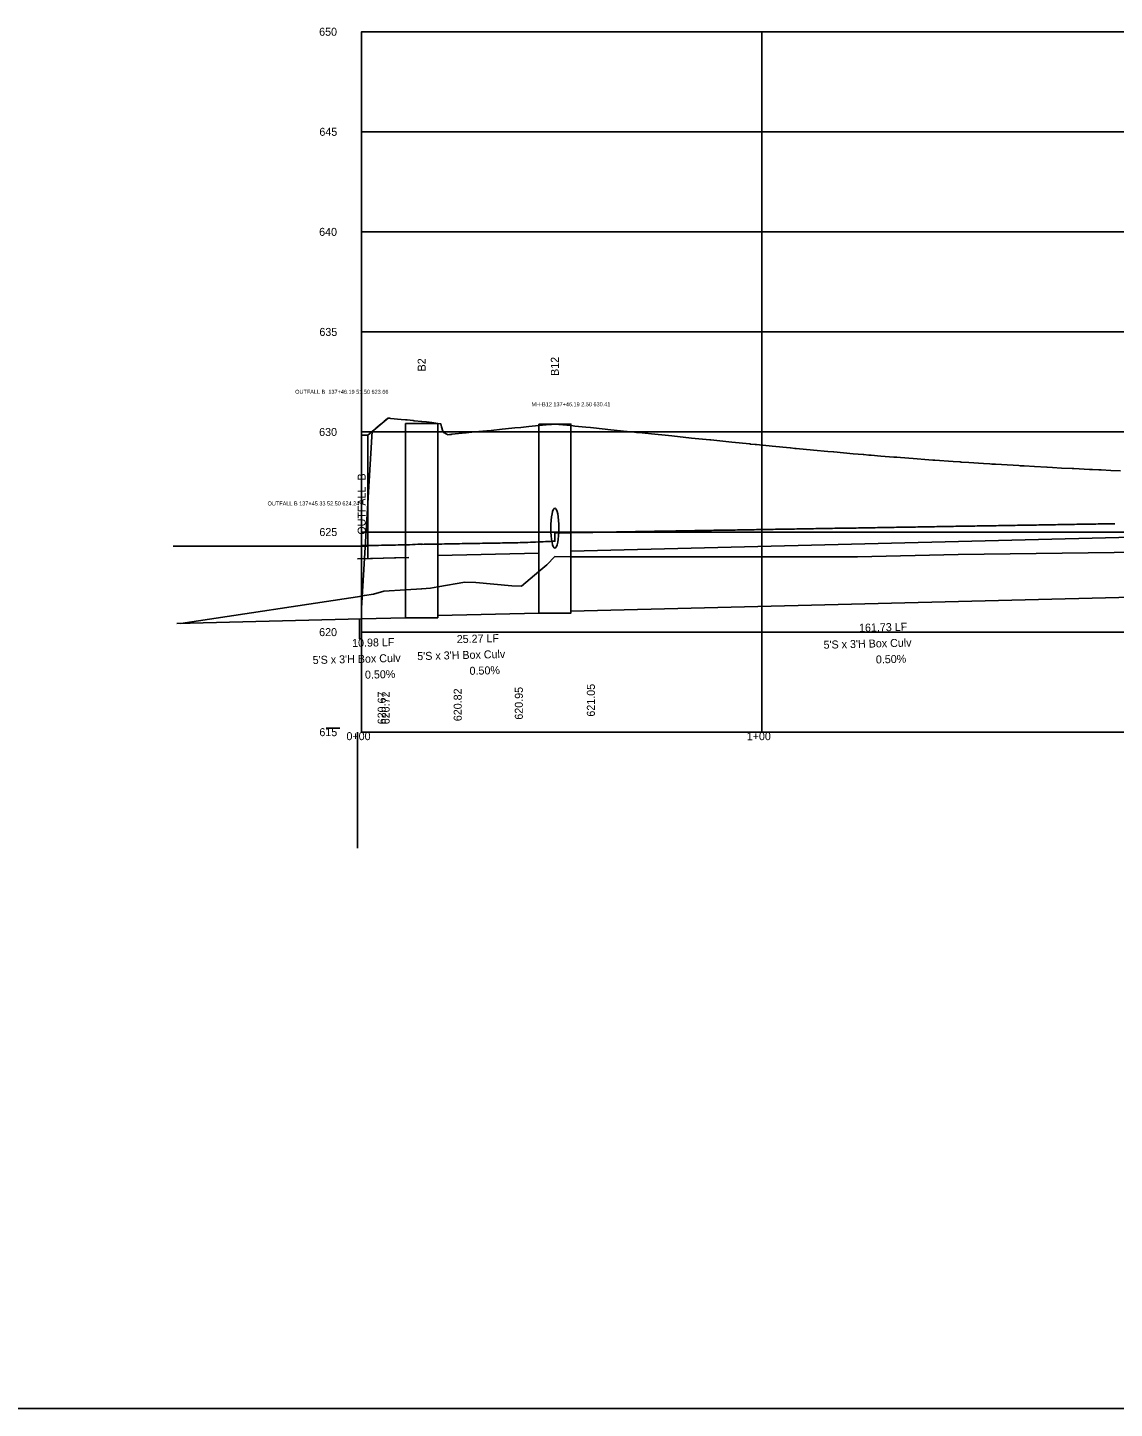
# Model space of a CAD drawing. Extents: x 2253035 to 2279930, y 13774972 to 13793443.
# Drawn here: x 2259878 to 2260149.5, y 13791972.5 to 13792317.5 of the extents above; entities that cross this region are included whole.
import ezdxf

# ---------------------------------------------------------------- set-up
doc = ezdxf.new("R2010")
doc.units = 0
for name, color, linetype in [('Default', 7, 'Continuous'), ('E_Utility_ATT_HH', 7, 'Continuous'), ('E_Utility_ATT_PR_PVC', 7, 'Continuous'), ('E_Utility_Electric_Service Pole Electric_SPLE_Description', 7, 'Continuous'), ('E_Utility_Telephone_Manhole Telephone_MHT_Description', 7, 'Continuous'), ('E_Utility_Telephone_Telephone Pedestal_TPED_Description', 7, 'Continuous'), ('E_Utility_Water_Fire Hydrant_FH_Description', 7, 'Continuous'), ('E_Utillity_Water_Water Line_12in', 7, 'Continuous'), ('E_Utillity_Water_Water Line_1in', 7, 'Continuous'), ('E_Utillity_Water_Water Line_4in', 7, 'Continuous'), ('E_Utillity_Water_Water Line_8in', 7, 'Continuous')]:
    doc.layers.add(name, color=color, linetype=linetype)

msp = doc.modelspace()

# ---------------------------------------------------------------- linework, layer by layer
at = {"layer": 'Default'}
for p, q in [((2260061.48, 13792141.44), (2260061.48, 13792316.44)), ((2259961.48, 13792291.44), (2261350.66, 13792291.44)), ((2259961.48, 13792266.44), (2261350.66, 13792266.44)), ((2259961.48, 13792241.44), (2261350.66, 13792241.44)), ((2259961.48, 13792216.44), (2261350.66, 13792216.44)), ((2259961.48, 13792191.44), (2261350.66, 13792191.44)), ((2259961.48, 13792166.44), (2261350.66, 13792166.44)), ((2258357.4, 13791972.48), (2265626.63, 13791972.48))]:
    msp.add_line(p, q, dxfattribs=at)
msp.add_lwpolyline([(2259961.48, 13792141.44), (2259961.48, 13792316.44), (2261350.66, 13792316.44), (2261350.66, 13792141.44)], close=True, dxfattribs=at)
at = {"layer": 'E_Utility_ATT_PR_PVC'}
for p, q in [((2260009.74, 13792191.61), (2260009.74, 13792191.21)), ((2259962.98, 13792187.94), (2259914.42, 13792187.94)), ((2259976.47, 13792188.56), (2259976.47, 13792188.36))]:
    msp.add_line(p, q, dxfattribs=at)
for points in [[(2259976.47, 13792188.36), (2259977.1, 13792188.38), (2259977.73, 13792188.39), (2259978.36, 13792188.4), (2259978.99, 13792188.41), (2259979.63, 13792188.42), (2259980.26, 13792188.43), (2259980.89, 13792188.44), (2259981.52, 13792188.45), (2259982.15, 13792188.46), (2259982.79, 13792188.47), (2259983.42, 13792188.48), (2259984.05, 13792188.49), (2259984.68, 13792188.5), (2259985.31, 13792188.52), (2259985.95, 13792188.53), (2259986.58, 13792188.54), (2259987.21, 13792188.55), (2259987.84, 13792188.56), (2259988.47, 13792188.57), (2259989.11, 13792188.58), (2259989.74, 13792188.59), (2259990.37, 13792188.6), (2259991, 13792188.61), (2259991.63, 13792188.62), (2259992.27, 13792188.63), (2259992.9, 13792188.65), (2259993.53, 13792188.66), (2259994.16, 13792188.67), (2259994.79, 13792188.68), (2259995.42, 13792188.69), (2259996.06, 13792188.7), (2259996.69, 13792188.71), (2259997.32, 13792188.72), (2259997.95, 13792188.73), (2259998.58, 13792188.74), (2259999.22, 13792188.75), (2259999.85, 13792188.76), (2260000.48, 13792188.77), (2260001.11, 13792188.79), (2260001.74, 13792188.8), (2260002.38, 13792188.82), (2260003.01, 13792188.85), (2260003.64, 13792188.88), (2260004.27, 13792188.9), (2260004.9, 13792188.93), (2260005.54, 13792188.96), (2260006.17, 13792188.98), (2260006.8, 13792189.01), (2260007.43, 13792189.04), (2260008.06, 13792189.06), (2260008.69, 13792189.09), (2260009.33, 13792189.12), (2260009.74, 13792189.13), (2260009.74, 13792191.61)], [(2260009.74, 13792191.21), (2260010.33, 13792191.22), (2260010.92, 13792191.23), (2260011.51, 13792191.24), (2260012.11, 13792191.25), (2260012.7, 13792191.26), (2260013.29, 13792191.27), (2260013.89, 13792191.28), (2260014.48, 13792191.29), (2260015.07, 13792191.3), (2260015.66, 13792191.31), (2260016.26, 13792191.32), (2260016.85, 13792191.32), (2260017.44, 13792191.33), (2260018.04, 13792191.34), (2260018.63, 13792191.35), (2260019.22, 13792191.36), (2260019.81, 13792191.37), (2260020.41, 13792191.38), (2260021, 13792191.39), (2260021.59, 13792191.4), (2260022.19, 13792191.41), (2260022.78, 13792191.42), (2260023.37, 13792191.43), (2260023.97, 13792191.44), (2260024.56, 13792191.45), (2260025.15, 13792191.46), (2260025.74, 13792191.47), (2260026.34, 13792191.48), (2260026.93, 13792191.49), (2260027.52, 13792191.5), (2260028.12, 13792191.51), (2260028.71, 13792191.52), (2260029.3, 13792191.53), (2260029.89, 13792191.54), (2260030.49, 13792191.55), (2260031.08, 13792191.56), (2260031.67, 13792191.57), (2260032.27, 13792191.58), (2260032.86, 13792191.59), (2260033.45, 13792191.6), (2260034.04, 13792191.61), (2260034.64, 13792191.62), (2260035.23, 13792191.63), (2260035.82, 13792191.64), (2260036.42, 13792191.65), (2260037.01, 13792191.66), (2260037.6, 13792191.67), (2260038.2, 13792191.68), (2260038.79, 13792191.69), (2260039.38, 13792191.7), (2260039.97, 13792191.71), (2260040.57, 13792191.72), (2260041.16, 13792191.73), (2260041.75, 13792191.74), (2260042.35, 13792191.75), (2260042.94, 13792191.76), (2260043.53, 13792191.77), (2260044.12, 13792191.78), (2260044.72, 13792191.79), (2260045.31, 13792191.8), (2260045.9, 13792191.81), (2260046.5, 13792191.82), (2260047.09, 13792191.83), (2260047.68, 13792191.84), (2260048.27, 13792191.85), (2260048.87, 13792191.86), (2260049.46, 13792191.87), (2260050.05, 13792191.88), (2260050.65, 13792191.88), (2260051.24, 13792191.89), (2260051.83, 13792191.9), (2260052.43, 13792191.91), (2260053.02, 13792191.92), (2260053.61, 13792191.93), (2260054.2, 13792191.94), (2260054.8, 13792191.95), (2260055.39, 13792191.96), (2260055.98, 13792191.97), (2260056.58, 13792191.98), (2260057.17, 13792191.99), (2260057.76, 13792192), (2260058.35, 13792192.01), (2260058.95, 13792192.02), (2260059.54, 13792192.03), (2260060.13, 13792192.04), (2260060.73, 13792192.05), (2260061.32, 13792192.06), (2260061.91, 13792192.07), (2260062.5, 13792192.08), (2260063.1, 13792192.09), (2260063.69, 13792192.1), (2260064.28, 13792192.11), (2260064.88, 13792192.12), (2260065.47, 13792192.13), (2260066.06, 13792192.14), (2260066.66, 13792192.15), (2260067.25, 13792192.16), (2260067.84, 13792192.17), (2260068.43, 13792192.18), (2260069.03, 13792192.19), (2260069.62, 13792192.2), (2260070.21, 13792192.21), (2260070.81, 13792192.22), (2260071.4, 13792192.23), (2260071.99, 13792192.24), (2260072.58, 13792192.25), (2260073.18, 13792192.26), (2260073.77, 13792192.27), (2260074.36, 13792192.28), (2260074.96, 13792192.29), (2260075.55, 13792192.3), (2260076.14, 13792192.31), (2260076.73, 13792192.32), (2260077.33, 13792192.33), (2260077.92, 13792192.34), (2260078.51, 13792192.35), (2260079.11, 13792192.36), (2260079.7, 13792192.37), (2260080.29, 13792192.38), (2260080.89, 13792192.39), (2260081.48, 13792192.4), (2260082.07, 13792192.41), (2260082.66, 13792192.42), (2260083.26, 13792192.43), (2260083.85, 13792192.43), (2260084.44, 13792192.44), (2260085.04, 13792192.45), (2260085.63, 13792192.46), (2260086.22, 13792192.47), (2260086.81, 13792192.48), (2260087.41, 13792192.49), (2260088, 13792192.5), (2260088.59, 13792192.51), (2260089.19, 13792192.52), (2260089.78, 13792192.53), (2260090.37, 13792192.54), (2260090.96, 13792192.55), (2260091.56, 13792192.56), (2260092.15, 13792192.57), (2260092.74, 13792192.58), (2260093.34, 13792192.59), (2260093.93, 13792192.6), (2260094.52, 13792192.61), (2260095.12, 13792192.62), (2260095.71, 13792192.63), (2260096.3, 13792192.64), (2260096.89, 13792192.65), (2260097.49, 13792192.66), (2260098.08, 13792192.67), (2260098.67, 13792192.68), (2260099.27, 13792192.69), (2260099.86, 13792192.7), (2260100.45, 13792192.71), (2260101.04, 13792192.72), (2260101.64, 13792192.73), (2260102.23, 13792192.74), (2260102.82, 13792192.75), (2260103.42, 13792192.76), (2260104.01, 13792192.77), (2260104.6, 13792192.78), (2260105.19, 13792192.79), (2260105.79, 13792192.8), (2260106.38, 13792192.81), (2260106.97, 13792192.82), (2260107.57, 13792192.83), (2260108.16, 13792192.84), (2260108.75, 13792192.85), (2260109.35, 13792192.86), (2260109.94, 13792192.87), (2260110.53, 13792192.88), (2260111.12, 13792192.89), (2260111.72, 13792192.9), (2260112.31, 13792192.91), (2260112.9, 13792192.92), (2260113.5, 13792192.93), (2260114.09, 13792192.94), (2260114.68, 13792192.95), (2260115.27, 13792192.96), (2260115.87, 13792192.97), (2260116.46, 13792192.98), (2260117.05, 13792192.99), (2260117.65, 13792192.99), (2260118.24, 13792193), (2260118.83, 13792193.01), (2260119.42, 13792193.02), (2260120.02, 13792193.03), (2260120.61, 13792193.04), (2260121.2, 13792193.05), (2260121.8, 13792193.06), (2260122.39, 13792193.07), (2260122.98, 13792193.08), (2260123.58, 13792193.09), (2260124.17, 13792193.1), (2260124.76, 13792193.11), (2260125.35, 13792193.12), (2260125.95, 13792193.13), (2260126.54, 13792193.14), (2260127.13, 13792193.15), (2260127.73, 13792193.16), (2260128.32, 13792193.17), (2260128.91, 13792193.18), (2260129.5, 13792193.19), (2260130.1, 13792193.2), (2260130.69, 13792193.21), (2260131.28, 13792193.22), (2260131.88, 13792193.23), (2260132.47, 13792193.24), (2260133.06, 13792193.25), (2260133.65, 13792193.26), (2260134.25, 13792193.27), (2260134.84, 13792193.28), (2260135.43, 13792193.29), (2260136.03, 13792193.3), (2260136.62, 13792193.31), (2260137.21, 13792193.32), (2260137.81, 13792193.33), (2260138.4, 13792193.34), (2260138.99, 13792193.35), (2260139.58, 13792193.36), (2260140.18, 13792193.37), (2260140.77, 13792193.38), (2260141.36, 13792193.39), (2260141.96, 13792193.4), (2260142.55, 13792193.41), (2260143.14, 13792193.42), (2260143.73, 13792193.43), (2260144.33, 13792193.44), (2260144.92, 13792193.45), (2260145.51, 13792193.46), (2260146.11, 13792193.47), (2260146.7, 13792193.48), (2260147.29, 13792193.49), (2260147.88, 13792193.5), (2260148.48, 13792193.51), (2260149.07, 13792193.52), (2260149.66, 13792193.53)], [(2259961.48, 13792188.04), (2259962.18, 13792188.06), (2259962.88, 13792188.07), (2259963.59, 13792188.08), (2259964.29, 13792188.09), (2259964.99, 13792188.11), (2259965.7, 13792188.12), (2259966.4, 13792188.13), (2259967.1, 13792188.14), (2259967.81, 13792188.16), (2259968.51, 13792188.17), (2259969.21, 13792188.18), (2259969.92, 13792188.19), (2259970.62, 13792188.21), (2259971.32, 13792188.22), (2259972.03, 13792188.23), (2259972.73, 13792188.25), (2259973.43, 13792188.28), (2259974.14, 13792188.31), (2259974.84, 13792188.34), (2259975.54, 13792188.37), (2259976.24, 13792188.4), (2259976.47, 13792188.41), (2259976.47, 13792188.56)]]:
    msp.add_lwpolyline(points, dxfattribs=at)
at = {"layer": 'E_Utility_Electric_Service Pole Electric_SPLE_Description'}
msp.add_line((2259960.48, 13792141.44), (2259960.48, 13792112.46), dxfattribs=at)
at = {"layer": 'E_Utility_Telephone_Manhole Telephone_MHT_Description'}
for p, q in [((2260010.47, 13792218.51), (2260010.47, 13792218.41)), ((2259961.48, 13792184.72), (2259961.48, 13792169.73)), ((2259956.03, 13792142.44), (2259952.58, 13792142.44))]:
    msp.add_line(p, q, dxfattribs=at)
msp.add_lwpolyline([(2259961.48, 13792169.75), (2259961.48, 13792164.75), (2259960.98, 13792164.75), (2259960.98, 13792169.75)], dxfattribs=at)
at = {"layer": 'E_Utility_Water_Fire Hydrant_FH_Description'}
for p, q in [((2259961.48, 13792184.95), (2259961.48, 13792215.66)), ((2259962.98, 13792215.66), (2259961.48, 13792215.66)), ((2259962.98, 13792184.79), (2259962.98, 13792215.66))]:
    msp.add_line(p, q, dxfattribs=at)
at = {"layer": 'E_Utillity_Water_Water Line_12in'}
for points in [[(2259972.47, 13792218.57), (2259980.47, 13792218.57), (2259980.47, 13792170.04), (2259972.47, 13792170.04)], [(2260005.74, 13792218.43), (2260013.74, 13792218.43), (2260013.74, 13792171.19), (2260005.74, 13792171.19)], [(2259961.48, 13792184.74), (2259961.48, 13792184.74), (2259961.48, 13792169.77), (2259961.48, 13792169.77)]]:
    msp.add_lwpolyline(points, close=True, dxfattribs=at)
at = {"layer": 'E_Utillity_Water_Water Line_1in'}
msp.add_line((2259961.49, 13792175.39), (2259916.3, 13792168.62), dxfattribs=at)
msp.add_lwpolyline([(2259961.48, 13792175.47), (2259961.48, 13792175.47), (2259961.48, 13792175.47), (2259962.18, 13792175.59), (2259964.41, 13792175.94), (2259967.06, 13792176.66), (2259972.47, 13792177.01), (2259972.47, 13792177.01), (2259976.47, 13792177.28), (2259976.47, 13792177.28), (2259978.69, 13792177.42), (2259980.47, 13792177.74), (2259980.47, 13792177.74), (2259987.29, 13792178.94), (2259990, 13792178.87), (2259998.99, 13792178.04), (2260001.37, 13792177.94), (2260005.74, 13792181.58), (2260005.74, 13792181.58), (2260007.77, 13792183.27), (2260009.74, 13792185.32), (2260009.74, 13792185.32), (2260013.74, 13792185.28), (2260013.74, 13792185.28), (2260085.31, 13792185.27), (2260110.5, 13792185.8), (2260175.47, 13792186.67)], dxfattribs=at)
at = {"layer": 'E_Utillity_Water_Water Line_4in'}
for p, q in [((2260013.74, 13792186.7), (2260175.47, 13792190.74)), ((2259961.48, 13792184.77), (2259972.47, 13792185.04)), ((2259980.47, 13792185.56), (2260005.74, 13792186.19)), ((2260013.74, 13792171.7), (2260175.47, 13792175.74)), ((2259961.48, 13792169.77), (2259972.47, 13792170.04)), ((2259980.47, 13792170.56), (2260005.74, 13792171.19))]:
    msp.add_line(p, q, dxfattribs=at)
msp.add_ellipse((2260009.74, 13792192.42), major_axis=(0, 5), ratio=0.2, dxfattribs=at)
at = {"layer": 'E_Utillity_Water_Water Line_8in'}
for p, q in [((2259968.06, 13792219.89), (2259962.98, 13792215.66)), ((2259973.26, 13792185.04), (2259960.48, 13792184.72)), ((2259961.48, 13792169.75), (2259915.3, 13792168.59))]:
    msp.add_line(p, q, dxfattribs=at)
msp.add_lwpolyline([(2259961.48, 13792172.44), (2259961.48, 13792172.44), (2259961.48, 13792172.44), (2259964.14, 13792216.62), (2259964.15, 13792216.62), (2259964.17, 13792216.64), (2259964.19, 13792216.66), (2259964.58, 13792216.98), (2259965.13, 13792217.44), (2259965.37, 13792217.64), (2259966.33, 13792218.44), (2259967.13, 13792219.11), (2259967.53, 13792219.44), (2259967.94, 13792219.79), (2259968, 13792219.84), (2259968.02, 13792219.85), (2259968.09, 13792219.9), (2259968.56, 13792219.86), (2259968.67, 13792219.85), (2259971.36, 13792219.59), (2259972.47, 13792219.48), (2259972.47, 13792219.48), (2259972.81, 13792219.44), (2259974.36, 13792219.28), (2259974.56, 13792219.26), (2259974.71, 13792219.25), (2259976.45, 13792219.07), (2259976.47, 13792219.07), (2259976.47, 13792219.07), (2259977.71, 13792218.94), (2259979.03, 13792218.8), (2259980.47, 13792218.57), (2259980.47, 13792218.57), (2259981.27, 13792218.44), (2259981.45, 13792217.74), (2259981.53, 13792217.44), (2259981.68, 13792216.86), (2259981.73, 13792216.67), (2259981.79, 13792216.44), (2259981.94, 13792216.35), (2259982.21, 13792216.2), (2259982.62, 13792215.97), (2259982.75, 13792215.89), (2259982.75, 13792215.89), (2259982.82, 13792215.85), (2259982.87, 13792215.82), (2259982.88, 13792215.81), (2259982.92, 13792215.79), (2259982.98, 13792215.76), (2259983.43, 13792215.8), (2259983.52, 13792215.81), (2259983.82, 13792215.84), (2259983.85, 13792215.85), (2259984.04, 13792215.87), (2259987.43, 13792216.21), (2259987.54, 13792216.22), (2259987.59, 13792216.22), (2259988.24, 13792216.29), (2259989.78, 13792216.44), (2259992.77, 13792216.74), (2259993.82, 13792216.85), (2259996.54, 13792217.12), (2259997.45, 13792217.21), (2259999.73, 13792217.44), (2260001.23, 13792217.59), (2260003.24, 13792217.8), (2260005.74, 13792218.05), (2260005.74, 13792218.05), (2260006.66, 13792218.14), (2260007.57, 13792218.22), (2260008.6, 13792218.32), (2260008.92, 13792218.35), (2260008.99, 13792218.36), (2260009.74, 13792218.43), (2260009.74, 13792218.43), (2260013.74, 13792218.02), (2260013.74, 13792218.02), (2260014.3, 13792217.96), (2260014.73, 13792217.92), (2260017.46, 13792217.64), (2260018.61, 13792217.52), (2260019.38, 13792217.44), (2260023.76, 13792216.99), (2260027.76, 13792216.59), (2260027.78, 13792216.58), (2260029.15, 13792216.44), (2260030.18, 13792216.34), (2260030.46, 13792216.31), (2260030.7, 13792216.29), (2260033.85, 13792215.96), (2260038.1, 13792215.53), (2260038.93, 13792215.44), (2260043.91, 13792214.93), (2260048.42, 13792214.47), (2260048.7, 13792214.44), (2260053.97, 13792213.9), (2260058.47, 13792213.44), (2260058.61, 13792213.43), (2260058.7, 13792213.42), (2260059.76, 13792213.31), (2260060.15, 13792213.28), (2260064.06, 13792212.88), (2260068.56, 13792212.44), (2260068.59, 13792212.44), (2260068.61, 13792212.44), (2260069.71, 13792212.34), (2260070.04, 13792212.3), (2260074.36, 13792211.9), (2260077.93, 13792211.57), (2260077.93, 13792211.57), (2260077.95, 13792211.57), (2260079.37, 13792211.45), (2260079.41, 13792211.44), (2260084.28, 13792211.02), (2260086.77, 13792210.81), (2260086.89, 13792210.8), (2260088.18, 13792210.69), (2260088.75, 13792210.64), (2260091.19, 13792210.44), (2260094.44, 13792210.18), (2260095.2, 13792210.12), (2260096.05, 13792210.06), (2260099.23, 13792209.81), (2260103.2, 13792209.51), (2260104.17, 13792209.44), (2260104.57, 13792209.41), (2260104.66, 13792209.41), (2260109.25, 13792209.08), (2260111, 13792208.96), (2260111.27, 13792208.94), (2260113.12, 13792208.82), (2260116.82, 13792208.58), (2260118.41, 13792208.47), (2260118.89, 13792208.44), (2260119.69, 13792208.39), (2260119.84, 13792208.39), (2260124.24, 13792208.12), (2260125.66, 13792208.03), (2260126.02, 13792208.01), (2260127.02, 13792207.96), (2260129.57, 13792207.81), (2260132.63, 13792207.64), (2260132.64, 13792207.64), (2260132.75, 13792207.63), (2260134.07, 13792207.56), (2260136.31, 13792207.44), (2260138.99, 13792207.31), (2260139.39, 13792207.29), (2260143.29, 13792207.1), (2260144.04, 13792207.06), (2260145.6, 13792206.99), (2260145.96, 13792206.97), (2260146.24, 13792206.96), (2260148.61, 13792206.85), (2260151.04, 13792206.75)], dxfattribs=at)

# ---------------------------------------------------------------- texts
at = {"layer": 'Default'}
for s, p in [('650', (2259950.86, 13792315.44)), ('645', (2259950.92, 13792290.44)), ('640', (2259950.86, 13792265.44)), ('635', (2259950.92, 13792240.44)), ('630', (2259950.86, 13792215.44)), ('625', (2259950.92, 13792190.44)), ('620', (2259950.86, 13792165.44)), ('615', (2259950.92, 13792140.44)), ('0+00', (2259957.68, 13792139.44)), ('1+00', (2260057.68, 13792139.44))]:
    msp.add_text(s, height=2, dxfattribs=at).set_placement(p)
at = {"layer": 'E_Utility_ATT_HH'}
for s, rotation, p in [('B2', 90, (2259977.47, 13792231.58)), ('B12', 90, (2260010.74, 13792230.45)), ('OUTFALL_B', 90, (2259962.48, 13792190.77)), ('161.73 LF', 1.4321, (2260085.75, 13792166.5)), ('10.98 LF', 1.4321, (2259959.12, 13792162.71)), ('25.27 LF', 1.4321, (2259985.25, 13792163.68)), ("5'S x 3'H Box Culv", 1.4321, (2260076.89, 13792162.28)), ("5'S x 3'H Box Culv", 1.4321, (2259949.27, 13792158.46)), ("5'S x 3'H Box Culv", 1.4321, (2259975.39, 13792159.43)), ('0.50%', 1.4321, (2260089.96, 13792158.6)), ('0.50%', 1.4321, (2259962.33, 13792154.79)), ('0.50%', 1.4321, (2259988.46, 13792155.76)), ('620.95', 90, (2260001.74, 13792144.56)), ('621.05', 90, (2260019.74, 13792145.32)), ('620.67', 90, (2259967.48, 13792143.4)), ('620.72', 90, (2259968.47, 13792143.41)), ('620.82', 90, (2259986.47, 13792144.18))]:
    msp.add_text(s, height=2, rotation=rotation, dxfattribs=at).set_placement(p)
at = {"layer": 'E_Utility_Telephone_Telephone Pedestal_TPED_Description'}
for s, p in [('OUTFALL B  137+46.19 51.50 623.66', (2259944.87, 13792225.98)), ('MH-B12 137+46.19 2.50 630.41', (2260003.93, 13792222.86)), ('OUTFALL B 137+45.33 52.50 624.24', (2259937.97, 13792198.08))]:
    msp.add_text(s, height=1, rotation=0, dxfattribs=at).set_placement(p)

doc.saveas('drawing.dxf')
